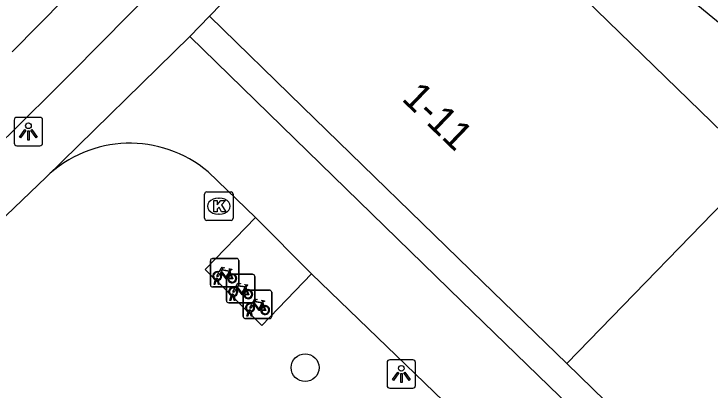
# Model space of a CAD drawing. Extents: x 162347 to 162868, y 381221 to 381813.
# Drawn here: x 162646.11 to 162670.57, y 381604.54 to 381617.75 of the extents above; entities that cross this region are included whole.
import ezdxf

# ---------------------------------------------------------------- set-up
doc = ezdxf.new("R2010")
doc.units = 0
for name, color, linetype in [('IMGEO_Boom', 7, 'Continuous'), ('IMGEO_Fietsenrek', 7, 'Continuous'), ('IMGEO_Kolk', 7, 'Continuous'), ('IMGEO_Lichtpunt', 7, 'Continuous'), ('IMGEO_Pand', 7, 'Continuous'), ('IMGEO_Pand_nummerreeks', 7, 'Continuous'), ('IMGEO_Rijbaan_lokaal_open', 7, 'Continuous'), ('IMGEO_Voetpad_open', 7, 'Continuous')]:
    doc.layers.add(name, color=color, linetype=linetype)

msp = doc.modelspace()

# ---------------------------------------------------------------- linework, layer by layer
at = {"layer": 'IMGEO_Boom'}
msp.add_circle((162656.341, 381605.331), 0.489, dxfattribs=at)
at = {"layer": 'IMGEO_Fietsenrek'}
for p, q in [((162653.087, 381609.163), (162653.928, 381609.163)), ((162653.928, 381609.163), (162653.087, 381609.163)), ((162653.012, 381608.238), (162653.012, 381609.079)), ((162653.012, 381609.079), (162653.012, 381608.238)), ((162654.012, 381609.088), (162654.012, 381608.247)), ((162654.012, 381608.247), (162654.012, 381609.088)), ((162653.699, 381608.712), (162653.735, 381608.617)), ((162653.139, 381608.247), (162653.178, 381608.407)), ((162653.208, 381608.395), (162653.173, 381608.247)), ((162653.25, 381608.419), (162653.249, 381608.423)), ((162653.291, 381608.247), (162653.257, 381608.389)), ((162653.281, 381608.43), (162653.282, 381608.423)), ((162653.289, 381608.393), (162653.324, 381608.247)), ((162653.572, 381607.684), (162653.572, 381608.525)), ((162653.572, 381608.525), (162653.572, 381607.684)), ((162653.647, 381608.609), (162654.488, 381608.609)), ((162654.488, 381608.609), (162653.647, 381608.609)), ((162654.572, 381608.534), (162654.572, 381607.693)), ((162654.572, 381607.693), (162654.572, 381608.534)), ((162653.937, 381608.163), (162653.096, 381608.163)), ((162653.096, 381608.163), (162653.937, 381608.163)), ((162653.173, 381608.247), (162653.139, 381608.247)), ((162653.324, 381608.247), (162653.291, 381608.247)), ((162654.259, 381608.158), (162654.295, 381608.063)), ((162654.167, 381607.127), (162654.167, 381607.968)), ((162654.167, 381607.968), (162654.167, 381607.127)), ((162654.242, 381608.052), (162655.083, 381608.052)), ((162655.083, 381608.052), (162654.242, 381608.052)), ((162655.167, 381607.977), (162655.167, 381607.136)), ((162655.167, 381607.136), (162655.167, 381607.977)), ((162653.699, 381607.693), (162653.738, 381607.853)), ((162653.733, 381607.693), (162653.699, 381607.693)), ((162653.768, 381607.841), (162653.733, 381607.693)), ((162653.81, 381607.865), (162653.809, 381607.869)), ((162653.851, 381607.693), (162653.817, 381607.835)), ((162653.841, 381607.876), (162653.842, 381607.869)), ((162653.849, 381607.839), (162653.884, 381607.693)), ((162653.884, 381607.693), (162653.851, 381607.693)), ((162654.497, 381607.609), (162653.656, 381607.609)), ((162653.656, 381607.609), (162654.497, 381607.609)), ((162654.854, 381607.601), (162654.89, 381607.506)), ((162654.294, 381607.136), (162654.333, 381607.296)), ((162654.363, 381607.284), (162654.328, 381607.136)), ((162654.405, 381607.308), (162654.404, 381607.312)), ((162654.446, 381607.136), (162654.412, 381607.278)), ((162654.436, 381607.319), (162654.437, 381607.312)), ((162654.444, 381607.282), (162654.479, 381607.136)), ((162655.092, 381607.052), (162654.251, 381607.052)), ((162654.251, 381607.052), (162655.092, 381607.052)), ((162654.328, 381607.136), (162654.294, 381607.136)), ((162654.479, 381607.136), (162654.446, 381607.136))]:
    msp.add_line(p, q, dxfattribs=at)
for points in [[(162653.346, 381608.637), (162653.294, 381608.547), (162653.254, 381608.522), (162653.255, 381608.569), (162653.31, 381608.663)], [(162653.325, 381608.689), (162653.42, 381608.853), (162653.506, 381608.839), (162653.508, 381608.83), (162653.452, 381608.819), (162653.425, 381608.774), (162653.681, 381608.733)], [(162653.621, 381608.445), (162653.571, 381608.445), (162653.38, 381608.696), (162653.361, 381608.664)], [(162653.668, 381608.708), (162653.411, 381608.749), (162653.394, 381608.72), (162653.561, 381608.5), (162653.668, 381608.708)], [(162653.716, 381608.61), (162653.686, 381608.687), (162653.577, 381608.469), (162653.62, 381608.469)], [(162653.681, 381608.733), (162653.706, 381608.782), (162653.7, 381608.786), (162653.677, 381608.79), (162653.665, 381608.797), (162653.664, 381608.8), (162653.666, 381608.805), (162653.761, 381608.79), (162653.763, 381608.78), (162653.753, 381608.767), (162653.741, 381608.761), (162653.727, 381608.767), (162653.699, 381608.712)], [(162653.65, 381608.469), (162653.77, 381608.468), (162653.726, 381608.582)], [(162653.746, 381608.589), (162653.801, 381608.444), (162653.651, 381608.444)], [(162653.885, 381608.135), (162653.98, 381608.299), (162654.066, 381608.285), (162654.068, 381608.276), (162654.012, 381608.265), (162653.985, 381608.22), (162654.241, 381608.179)], [(162654.181, 381607.891), (162654.131, 381607.891), (162653.94, 381608.142), (162653.921, 381608.11)], [(162654.228, 381608.154), (162653.971, 381608.195), (162653.954, 381608.166), (162654.121, 381607.946), (162654.228, 381608.154)], [(162654.241, 381608.179), (162654.266, 381608.228), (162654.26, 381608.232), (162654.237, 381608.236), (162654.225, 381608.243), (162654.224, 381608.246), (162654.226, 381608.251), (162654.321, 381608.236), (162654.323, 381608.226), (162654.313, 381608.213), (162654.301, 381608.207), (162654.287, 381608.213), (162654.259, 381608.158)], [(162653.906, 381608.083), (162653.854, 381607.993), (162653.814, 381607.968), (162653.815, 381608.015), (162653.87, 381608.109)], [(162654.276, 381608.056), (162654.246, 381608.133), (162654.137, 381607.915), (162654.18, 381607.915)], [(162654.21, 381607.915), (162654.33, 381607.914), (162654.286, 381608.028)], [(162654.306, 381608.035), (162654.361, 381607.89), (162654.211, 381607.89)], [(162654.48, 381607.578), (162654.575, 381607.742), (162654.661, 381607.728), (162654.663, 381607.719), (162654.607, 381607.708), (162654.58, 381607.663), (162654.836, 381607.622)], [(162654.836, 381607.622), (162654.861, 381607.671), (162654.855, 381607.675), (162654.832, 381607.679), (162654.82, 381607.686), (162654.819, 381607.689), (162654.821, 381607.694), (162654.916, 381607.679), (162654.918, 381607.669), (162654.908, 381607.656), (162654.896, 381607.65), (162654.882, 381607.656), (162654.854, 381607.601)], [(162654.501, 381607.526), (162654.449, 381607.436), (162654.409, 381607.411), (162654.41, 381607.458), (162654.465, 381607.552)], [(162654.776, 381607.334), (162654.726, 381607.334), (162654.535, 381607.585), (162654.516, 381607.553)], [(162654.823, 381607.597), (162654.566, 381607.638), (162654.549, 381607.609), (162654.716, 381607.389), (162654.823, 381607.597)], [(162654.871, 381607.499), (162654.841, 381607.576), (162654.732, 381607.358), (162654.775, 381607.358)], [(162654.805, 381607.358), (162654.925, 381607.357), (162654.881, 381607.471)], [(162654.901, 381607.478), (162654.956, 381607.333), (162654.806, 381607.333)]]:
    msp.add_lwpolyline(points, dxfattribs=at)
for centre, radius, start, end in [((162653.09, 381609.085), 0.0779, 92.4484, 184.2845), ((162653.09, 381609.085), 0.0779, 92.4484, 184.2845), ((162653.934, 381609.085), 0.0779, 2.4484, 94.2845), ((162653.934, 381609.085), 0.0779, 2.4484, 94.2845), ((162653.252, 381608.548), 0.159, 62.6766, 242.1369), ((162653.252, 381608.548), 0.129, 63.3192, 238.903), ((162653.252, 381608.548), 0.129, 283.6043, 43.4302), ((162653.252, 381608.548), 0.159, 283.5766, 46.6042), ((162653.232, 381608.419), 0.0499, 12.8025, 158.6934), ((162653.252, 381608.548), 0.159, 253.9967, 271.7867), ((162653.232, 381608.419), 0.0174, 12.8025, 163.4502), ((162653.252, 381608.548), 0.129, 253.415, 269.0204), ((162653.65, 381608.531), 0.0779, 92.4484, 184.2845), ((162653.65, 381608.531), 0.0779, 92.4484, 184.2845), ((162653.779, 381608.464), 0.159, 113.3408, 178.3217), ((162653.779, 381608.464), 0.159, 187.0065, 105.7708), ((162653.779, 381608.464), 0.129, 113.923, 177.9556), ((162653.779, 381608.464), 0.129, 188.6715, 104.5883), ((162654.494, 381608.531), 0.0779, 2.4484, 94.2845), ((162654.494, 381608.531), 0.0779, 2.4484, 94.2845), ((162653.09, 381608.241), 0.0779, 182.4484, 274.2845), ((162653.09, 381608.241), 0.0779, 182.4484, 274.2845), ((162653.812, 381607.994), 0.159, 62.6766, 242.1369), ((162653.934, 381608.241), 0.0779, 272.4484, 4.2845), ((162653.934, 381608.241), 0.0779, 272.4484, 4.2845), ((162653.812, 381607.994), 0.129, 63.3192, 238.903), ((162653.792, 381607.865), 0.0499, 12.8025, 158.6934), ((162653.812, 381607.994), 0.129, 283.6043, 43.4302), ((162653.812, 381607.994), 0.159, 283.5766, 46.6042), ((162654.245, 381607.974), 0.0779, 92.4484, 184.2845), ((162654.245, 381607.974), 0.0779, 92.4484, 184.2845), ((162654.339, 381607.91), 0.159, 113.3408, 178.3217), ((162654.339, 381607.91), 0.159, 187.0065, 105.7708), ((162654.339, 381607.91), 0.129, 113.923, 177.9556), ((162654.339, 381607.91), 0.129, 188.6715, 104.5883), ((162655.089, 381607.974), 0.0779, 2.4484, 94.2845), ((162655.089, 381607.974), 0.0779, 2.4484, 94.2845), ((162653.65, 381607.687), 0.0779, 182.4484, 274.2845), ((162653.65, 381607.687), 0.0779, 182.4484, 274.2845), ((162653.812, 381607.994), 0.159, 253.9967, 271.7867), ((162653.792, 381607.865), 0.0174, 12.8025, 163.4502), ((162653.812, 381607.994), 0.129, 253.415, 269.0204), ((162654.494, 381607.687), 0.0779, 272.4484, 4.2845), ((162654.494, 381607.687), 0.0779, 272.4484, 4.2845), ((162654.407, 381607.437), 0.159, 62.6766, 242.1369), ((162654.407, 381607.437), 0.129, 63.3192, 238.903), ((162654.407, 381607.437), 0.129, 283.6043, 43.4302), ((162654.407, 381607.437), 0.159, 283.5766, 46.6042), ((162654.934, 381607.353), 0.159, 113.3408, 178.3217), ((162654.934, 381607.353), 0.159, 187.0065, 105.7708), ((162654.934, 381607.353), 0.129, 113.923, 177.9556), ((162654.934, 381607.353), 0.129, 188.6715, 104.5883), ((162654.387, 381607.308), 0.0499, 12.8025, 158.6934), ((162654.407, 381607.437), 0.159, 253.9967, 271.7867), ((162654.387, 381607.308), 0.0174, 12.8025, 163.4502), ((162654.407, 381607.437), 0.129, 253.415, 269.0204), ((162654.245, 381607.13), 0.0779, 182.4484, 274.2845), ((162654.245, 381607.13), 0.0779, 182.4484, 274.2845), ((162655.089, 381607.13), 0.0779, 272.4484, 4.2845), ((162655.089, 381607.13), 0.0779, 272.4484, 4.2845)]:
    msp.add_arc(centre, radius, start, end, dxfattribs=at)
at = {"layer": 'IMGEO_Kolk'}
for p, q in [((162652.809, 381610.574), (162652.809, 381611.426)), ((162652.884, 381611.5), (162653.736, 381611.5)), ((162653.81, 381611.426), (162653.81, 381610.574)), ((162653.297, 381611.28), (162653.322, 381611.28)), ((162653.32, 381610.72), (162653.295, 381610.72)), ((162653.736, 381610.5), (162652.884, 381610.5))]:
    msp.add_line(p, q, dxfattribs=at)
for points in [[(162652.809, 381610.574), (162652.809, 381611.426)], [(162652.884, 381611.5), (162653.736, 381611.5)], [(162653.81, 381611.426), (162653.81, 381610.574)], [(162653.13, 381611.2), (162653.253, 381611.2), (162653.253, 381611.049), (162653.383, 381611.2), (162653.547, 381611.2), (162653.401, 381611.049), (162653.554, 381610.8), (162653.402, 381610.8), (162653.317, 381610.964), (162653.253, 381610.897), (162653.253, 381610.8), (162653.13, 381610.8), (162653.13, 381611.2)], [(162653.736, 381610.5), (162652.884, 381610.5)]]:
    msp.add_lwpolyline(points, dxfattribs=at)
for centre, start, end in [((162652.886, 381611.424), 91.552, 178.448), ((162652.886, 381611.424), 91.552, 178.448), ((162653.734, 381611.424), 1.552, 88.448), ((162653.734, 381611.424), 1.552, 88.448), ((162652.886, 381610.576), 181.552, 268.448), ((162652.886, 381610.576), 181.552, 268.448), ((162653.734, 381610.576), 271.552, 358.448), ((162653.734, 381610.576), 271.552, 358.448)]:
    msp.add_arc(centre, 0.0765, start, end, dxfattribs=at)
for centre, major_axis, ratio, start_param, end_param in [((162653.296, 381611), (-0.387, 0.002), 0.722429, 4.712389, 7.853982), ((162653.321, 381611), (-0.39, 0.002), 0.717154, 1.570796, 4.712389)]:
    msp.add_ellipse(centre, major_axis=major_axis, ratio=ratio, start_param=start_param, end_param=end_param, dxfattribs=at)
at = {"layer": 'IMGEO_Lichtpunt'}
for p, q in [((162646.119, 381614.022), (162646.119, 381613.215)), ((162646.119, 381614.022), (162646.119, 381613.215)), ((162647.021, 381614.117), (162646.213, 381614.117)), ((162647.021, 381614.117), (162646.213, 381614.117)), ((162647.115, 381613.215), (162647.115, 381614.022)), ((162647.115, 381613.215), (162647.115, 381614.022)), ((162646.213, 381613.121), (162647.021, 381613.121)), ((162646.213, 381613.121), (162647.021, 381613.121)), ((162659.221, 381605.511), (162659.221, 381604.704)), ((162659.221, 381605.511), (162659.221, 381604.704)), ((162660.123, 381605.606), (162659.315, 381605.606)), ((162660.123, 381605.606), (162659.315, 381605.606)), ((162660.217, 381604.704), (162660.217, 381605.511)), ((162660.217, 381604.704), (162660.217, 381605.511)), ((162659.315, 381604.61), (162660.123, 381604.61)), ((162659.315, 381604.61), (162660.123, 381604.61))]:
    msp.add_line(p, q, dxfattribs=at)
for points in [[(162646.493, 381613.686), (162646.532, 381613.658), (162646.344, 381613.396), (162646.306, 381613.423), (162646.493, 381613.686)], [(162646.595, 381613.638), (162646.642, 381613.638), (162646.642, 381613.316), (162646.595, 381613.316), (162646.595, 381613.638)], [(162646.705, 381613.658), (162646.743, 381613.685), (162646.93, 381613.423), (162646.891, 381613.395), (162646.705, 381613.658)], [(162659.595, 381605.175), (162659.634, 381605.147), (162659.446, 381604.885), (162659.408, 381604.912), (162659.595, 381605.175)], [(162659.697, 381605.127), (162659.744, 381605.127), (162659.744, 381604.805), (162659.697, 381604.805), (162659.697, 381605.127)], [(162659.807, 381605.147), (162659.845, 381605.174), (162660.032, 381604.912), (162659.993, 381604.884), (162659.807, 381605.147)]]:
    msp.add_lwpolyline(points, dxfattribs=at)
for centre in [(162646.618, 381613.82), (162659.72, 381605.309)]:
    msp.add_circle(centre, 0.0994, dxfattribs=at)
for centre, start, end in [((162646.213, 381614.022), 90, 180), ((162646.213, 381614.022), 90, 180), ((162647.021, 381614.022), 0, 90), ((162647.021, 381614.022), 0, 90), ((162646.213, 381613.215), 180, 270), ((162646.213, 381613.215), 180, 270), ((162647.021, 381613.215), 270, 0), ((162647.021, 381613.215), 270, 360), ((162659.315, 381605.511), 90, 180), ((162659.315, 381605.511), 90, 180), ((162660.123, 381605.511), 0, 90), ((162660.123, 381605.511), 0, 90), ((162659.315, 381604.704), 180, 270), ((162659.315, 381604.704), 180, 270), ((162660.123, 381604.704), 270, 0), ((162660.123, 381604.704), 270, 360)]:
    msp.add_arc(centre, 0.0946, start, end, dxfattribs=at)
at = {"layer": 'IMGEO_Pand'}
for points in [[(162652.976, 381617.664), (162659.686, 381624.575)], [(162672.242, 381612.385), (162659.686, 381624.575)], [(162652.976, 381617.664), (162656.251, 381614.485), (162662.563, 381608.357), (162665.532, 381605.474)], [(162665.532, 381605.474), (162672.242, 381612.385)], [(162665.532, 381605.474), (162668.681, 381602.417), (162675.103, 381596.183), (162678.089, 381593.285)]]:
    msp.add_lwpolyline(points, dxfattribs=at)
at = {"layer": 'IMGEO_Rijbaan_lokaal_open'}
for points in [[(162701.58, 381592.223), (162660.865, 381625.672)], [(162646.045, 381616.42), (162650.694, 381621.134)]]:
    msp.add_lwpolyline(points, dxfattribs=at)
at = {"layer": 'IMGEO_Voetpad_open'}
for points in [[(162651.186, 381618.784), (162648.124, 381615.672)], [(162652.285, 381616.955), (162652.976, 381617.664)], [(162652.285, 381616.955), (162647.237, 381612.021)], [(162689.987, 381580.301), (162686.832, 381583.418), (162680.473, 381589.574), (162674.343, 381595.464), (162667.976, 381601.726), (162661.834, 381607.667), (162655.527, 381613.812), (162652.285, 381616.955)], [(162652.937, 381612.199), (162654.594, 381610.607)], [(162630.312, 381595.808), (162647.237, 381612.021)], [(162656.566, 381608.626), (162654.824, 381606.815), (162652.827, 381608.774), (162654.594, 381610.607)], [(162654.594, 381610.607), (162656.566, 381608.626)], [(162656.566, 381608.626), (162668.158, 381597.447)]]:
    msp.add_lwpolyline(points, dxfattribs=at)
for centre, radius, start, end in [((162453.187, 381810.05), 275.288, 312.58981, 315.08241), ((162650.186, 381608.949), 4.258, 49.7543, 133.823)]:
    msp.add_arc(centre, radius, start, end, dxfattribs=at)

# ---------------------------------------------------------------- texts
at = {"layer": 'IMGEO_Pand_nummerreeks'}
msp.add_text('1-11', height=1, rotation=316.1597, dxfattribs=at).set_placement((162659.701, 381614.734))

doc.saveas('drawing.dxf')
